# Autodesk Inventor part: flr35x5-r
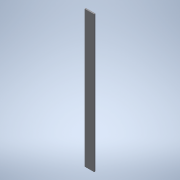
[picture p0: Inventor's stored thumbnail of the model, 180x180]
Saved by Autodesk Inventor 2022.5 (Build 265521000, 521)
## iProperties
Created: 2016-12
Part Number: flr35x5-r
Material: 一般
Document SubType Name: Modeling
Designer: imaocorp
Density: 1 g/cm^3
Appearance: 既定
Author: imaocorp
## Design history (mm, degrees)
node "flr35x5-r.x_t1"
node "flr35x5-r"
node "Base1"
